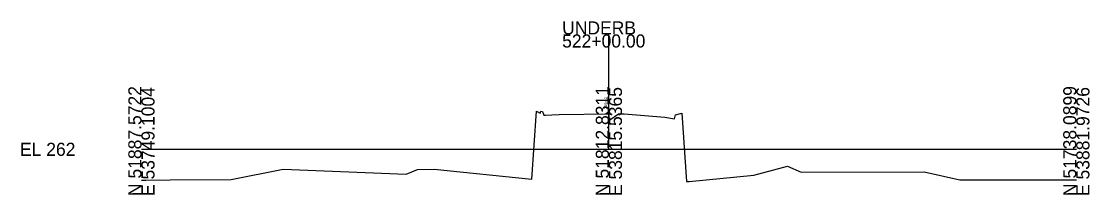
# Model space of a CAD drawing. Extents: x 12366 to 12594, y 96215 to 101752.
# Drawn here: x 12365.6 to 12594.1, y 100714.9 to 100752 of the extents above; entities that cross this region are included whole.
import ezdxf

# ---------------------------------------------------------------- set-up
doc = ezdxf.new("R2010")
doc.units = 0
for name, color, linetype in [('Level 10', 7, 'Continuous'), ('Level 60', 7, 'Continuous'), ('Level 63', 7, 'Continuous')]:
    doc.layers.add(name, color=color, linetype=linetype)

msp = doc.modelspace()

# ---------------------------------------------------------------- linework, layer by layer
at = {"layer": 'Level 60'}
for p, q in [((12474.83, 100718.27), (12475.8, 100732.8)), ((12475.8, 100732.8), (12476.57, 100732.39)), ((12476.57, 100732.39), (12476.71, 100732.83)), ((12476.71, 100732.83), (12477.13, 100732.76)), ((12477.13, 100732.76), (12477.39, 100731.94)), ((12480.66, 100732.06), (12491.32, 100732.26)), ((12491.32, 100732.26), (12491.32, 100730.78)), ((12491.32, 100730.78), (12493.35, 100732.22)), ((12493.35, 100732.22), (12494.54, 100732.21)), ((12494.54, 100732.21), (12503.26, 100731.5)), ((12505.57, 100732.02), (12506.91, 100732.39)), ((12506.91, 100732.39), (12507.9, 100717.75)), ((12477.39, 100731.94), (12477.71, 100731.95)), ((12477.71, 100731.95), (12479.06, 100732.03)), ((12479.06, 100732.03), (12480.66, 100732.06)), ((12503.26, 100731.5), (12505.3, 100731.18)), ((12505.3, 100731.18), (12505.57, 100732.02)), ((12522.29, 100719.13), (12529.51, 100721.05)), ((12529.51, 100721.05), (12532.46, 100719.76)), ((12410.48, 100718.16), (12421.6, 100720.4)), ((12421.6, 100720.4), (12447.92, 100719.3)), ((12447.92, 100719.3), (12450.34, 100720.35)), ((12450.34, 100720.35), (12453.89, 100720.39)), ((12453.89, 100720.39), (12474.83, 100718.27)), ((12508.5, 100717.76), (12522.29, 100719.13)), ((12532.46, 100719.76), (12558.74, 100719.84)), ((12558.74, 100719.84), (12566.35, 100718.12)), ((12391.3, 100718.06), (12392.25, 100718.07)), ((12392.25, 100718.07), (12397.44, 100718.08)), ((12397.44, 100718.08), (12410.48, 100718.16)), ((12507.9, 100717.75), (12508.5, 100717.76)), ((12566.35, 100718.12), (12576.92, 100718.12)), ((12576.92, 100718.12), (12591.3, 100718.08))]:
    msp.add_line(p, q, dxfattribs=at)
at = {"layer": 'Level 63'}
for p, q in [((12491.3, 100724.64), (12491.3, 100749.21)), ((12391.3, 100724.64), (12491.3, 100724.64)), ((12491.3, 100724.64), (12591.3, 100724.64))]:
    msp.add_line(p, q, dxfattribs=at)

# ---------------------------------------------------------------- texts
at = {"layer": 'Level 10'}
msp.add_text('269.62', height=0.6, rotation=90, dxfattribs=at).set_placement((12490.9, 100733.26))
at = {"layer": 'Level 63'}
for s, p in [('UNDERB', (12481.3, 100749.21)), ('522+00.00', (12481.3, 100746.41)), ('EL 262', (12365.31, 100723.24))]:
    msp.add_text(s, height=2.8, dxfattribs=at).set_placement(p)
for s, p in [('N 51887.5722', (12391.3, 100714.64)), ('E 53749.1004', (12394.1, 100714.64)), ('N 51812.8311', (12491.3, 100714.64)), ('E 53815.5365', (12494.1, 100714.64)), ('N 51738.0899', (12591.3, 100714.64)), ('E 53881.9726', (12594.1, 100714.64))]:
    msp.add_text(s, height=2.8, rotation=90, dxfattribs=at).set_placement(p)

doc.saveas('drawing.dxf')
